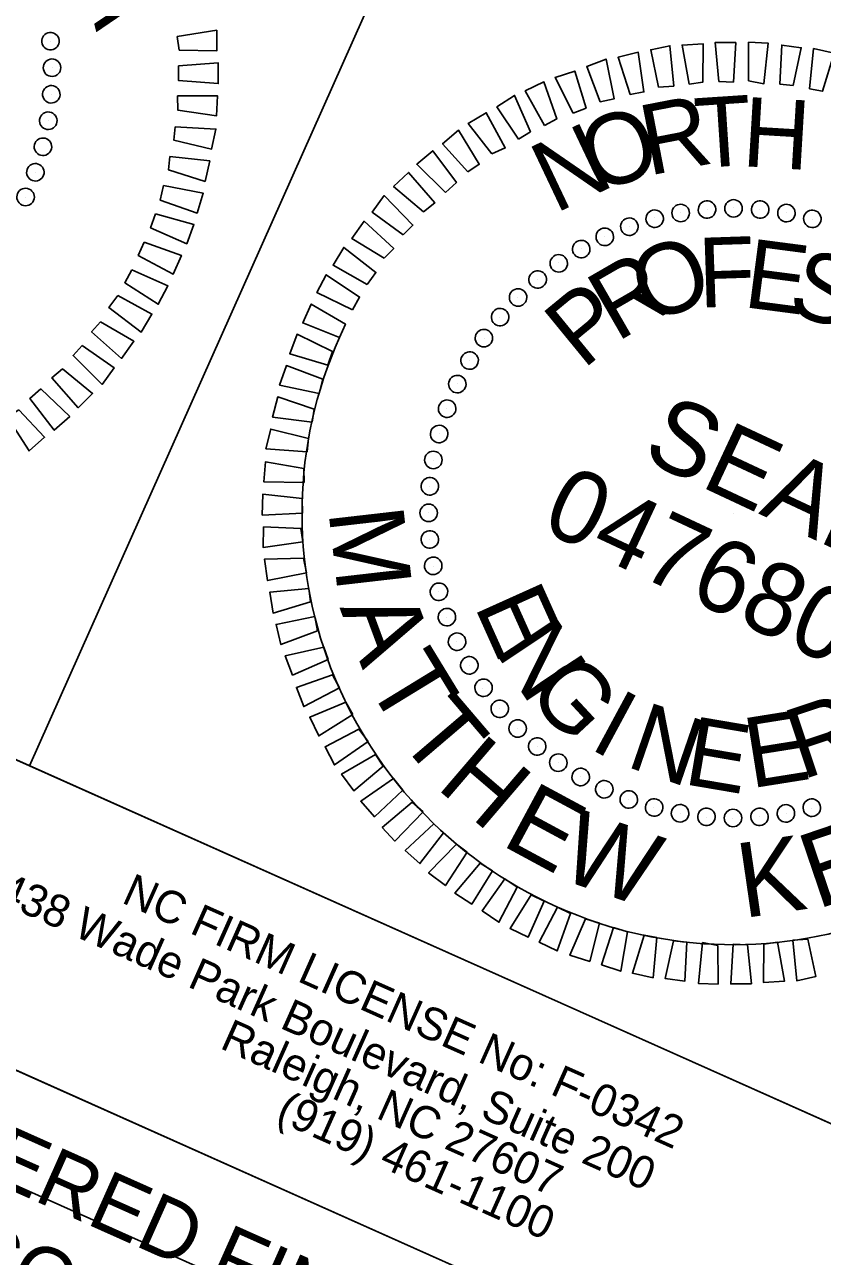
# Model space of a CAD drawing. Extents: x 2297991 to 2299183, y 599186 to 600200.
# Drawn here: x 2299075.6 to 2299120, y 599694 to 599762.5 of the extents above; entities that cross this region are included whole.
import ezdxf

# ---------------------------------------------------------------- set-up
doc = ezdxf.new("R2010")
doc.units = 0
for name, color, linetype in [('Default', 7, 'Continuous'), ('Exist DTM Drainline Cogo Point CELL', 7, 'Continuous'), ('Exist Roads Curbs Cogo Elevation', 7, 'Continuous'), ('Exist Roads Curbs Cogo Number', 7, 'Continuous'), ('Exist Roads EOP Cogo Comment', 7, 'Continuous'), ('Exist Roads EOP Cogo Elevation', 7, 'Continuous'), ('Exist Roads EOP Other Cogo Number', 7, 'Continuous'), ('Exist Roads EOP Other Cogo Point CELL', 7, 'Continuous')]:
    doc.layers.add(name, color=color, linetype=linetype)

# ---------------------------------------------------------------- blocks, each defined once
blk = doc.blocks.new('POINT_DISPLAY')
at = {"layer": 'Default'}
blk.add_line((0, 0), (0, 0), dxfattribs=at)

msp = doc.modelspace()

# ---------------------------------------------------------------- linework, layer by layer
at = {"layer": 'Exist DTM Drainline Cogo Point CELL'}
for points in [[(2299048.604, 599807.413), (2299103.421, 599782.943), (2299075.906, 599721.305), (2299021.089, 599745.774)], [(2299103.421, 599782.943), (2299158.21, 599758.486), (2299130.696, 599696.848), (2299075.906, 599721.305)]]:
    msp.add_lwpolyline(points, close=True, dxfattribs=at)
at = {"layer": 'Exist Roads Curbs Cogo Elevation'}
msp.add_lwpolyline([(2299021.089, 599745.774), (2299130.668, 599696.86), (2299124.249, 599682.479), (2299014.67, 599731.393)], close=True, dxfattribs=at)
at = {"layer": 'Exist Roads Curbs Cogo Number'}
msp.add_line((2299014.67, 599731.393), (2299124.269, 599682.47), dxfattribs=at)
at = {"layer": 'Exist Roads EOP Cogo Comment'}
msp.add_lwpolyline([(2298353.139, 600126.103), (2298108.588, 599578.22), (2298903.031, 599223.593), (2299108.187, 599683.241), (2298998.588, 599732.165), (2299037.976, 599820.403)], close=True, dxfattribs=at)
msp.add_arc((2299115.02, 599735.33), 23.962, 155.94476, 335.94476, dxfattribs=at)
at = {"layer": 'Exist Roads EOP Other Cogo Number'}
for p, q in [((2299112.083, 599752.016), (2299112.083, 599752.016)), ((2299113.57, 599752.202), (2299113.57, 599752.202)), ((2299115.047, 599752.282), (2299115.047, 599752.282)), ((2299116.5, 599752.225), (2299116.5, 599752.225)), ((2299117.96, 599752.017), (2299117.96, 599752.017)), ((2299110.66, 599751.727), (2299110.66, 599751.727)), ((2299119.426, 599751.658), (2299119.426, 599751.658)), ((2299107.879, 599750.714), (2299107.879, 599750.714)), ((2299109.23, 599751.257), (2299109.23, 599751.257)), ((2299106.566, 599750.007), (2299106.566, 599750.007)), ((2299105.3, 599749.241), (2299105.3, 599749.241)), ((2299104.147, 599748.314), (2299104.147, 599748.314)), ((2299103.042, 599747.329), (2299103.042, 599747.329)), ((2299102.033, 599746.227), (2299102.033, 599746.227)), ((2299101.178, 599745.057), (2299101.178, 599745.057)), ((2299100.37, 599743.828), (2299100.37, 599743.828)), ((2299099.673, 599742.513), (2299099.673, 599742.513)), ((2299099.098, 599741.143), (2299099.098, 599741.143)), ((2299098.692, 599739.736), (2299098.692, 599739.736)), ((2299098.333, 599738.27), (2299098.333, 599738.27)), ((2299098.125, 599736.81), (2299098.125, 599736.81)), ((2299098.068, 599735.357), (2299098.068, 599735.357)), ((2299115.02, 599735.33), (2299115.02, 599735.33)), ((2299098.147, 599733.88), (2299098.147, 599733.88)), ((2299098.334, 599732.393), (2299098.334, 599732.393)), ((2299098.623, 599730.97), (2299098.623, 599730.97)), ((2299099.093, 599729.54), (2299099.093, 599729.54)), ((2299099.636, 599728.189), (2299099.636, 599728.189)), ((2299100.343, 599726.876), (2299100.343, 599726.876)), ((2299101.109, 599725.61), (2299101.109, 599725.61)), ((2299102.035, 599724.457), (2299102.035, 599724.457)), ((2299103.02, 599723.352), (2299103.02, 599723.352)), ((2299104.122, 599722.343), (2299104.122, 599722.343)), ((2299105.293, 599721.488), (2299105.293, 599721.488)), ((2299106.522, 599720.68), (2299106.522, 599720.68)), ((2299107.837, 599719.983), (2299107.837, 599719.983)), ((2299109.206, 599719.408), (2299109.206, 599719.408)), ((2299110.614, 599719.001), (2299110.614, 599719.001)), ((2299112.08, 599718.643), (2299112.08, 599718.643)), ((2299113.54, 599718.435), (2299113.54, 599718.435)), ((2299116.47, 599718.457), (2299116.47, 599718.457)), ((2299117.957, 599718.643), (2299117.957, 599718.643)), ((2299119.38, 599718.932), (2299119.38, 599718.932)), ((2299114.993, 599718.377), (2299114.993, 599718.377))]:
    msp.add_line(p, q, dxfattribs=at)
for points in [[(2299109.287, 599758.586), (2299108.622, 599760.657), (2299109.743, 599760.933), (2299110.051, 599758.726)], [(2299110.871, 599758.988), (2299110.432, 599761.069), (2299111.495, 599761.297), (2299111.714, 599759.055)], [(2299112.571, 599759.153), (2299112.173, 599761.327), (2299113.349, 599761.393), (2299113.321, 599759.262)], [(2299114.226, 599759.302), (2299114.01, 599761.468), (2299115.158, 599761.473), (2299115.028, 599759.276)], [(2299115.871, 599759.343), (2299115.868, 599761.489), (2299116.957, 599761.446), (2299116.724, 599759.184)], [(2299117.601, 599759.162), (2299117.718, 599761.328), (2299118.797, 599761.179), (2299118.345, 599759.089)], [(2299119.259, 599758.903), (2299119.479, 599761.133), (2299120.623, 599760.881), (2299119.975, 599758.768)], [(2299107.628, 599758.181), (2299106.877, 599760.143), (2299107.947, 599760.552), (2299108.406, 599758.351)], [(2299106.129, 599757.557), (2299105.121, 599759.522), (2299106.208, 599759.887), (2299106.842, 599757.83)], [(2299104.528, 599756.867), (2299103.462, 599758.784), (2299104.497, 599759.283), (2299105.207, 599757.229)], [(2299103.08, 599756.109), (2299101.884, 599757.899), (2299102.868, 599758.532), (2299103.742, 599756.515)], [(2299101.606, 599755.289), (2299100.292, 599756.984), (2299101.294, 599757.571), (2299102.346, 599755.623)], [(2299100.274, 599754.294), (2299098.862, 599755.848), (2299099.75, 599756.597), (2299100.906, 599754.714)], [(2299099.025, 599753.151), (2299097.431, 599754.713), (2299098.319, 599755.462), (2299099.636, 599753.692)], [(2299097.803, 599752.07), (2299096.14, 599753.478), (2299096.967, 599754.254), (2299098.431, 599752.566)], [(2299096.681, 599750.797), (2299094.949, 599752.051), (2299095.619, 599752.972), (2299097.216, 599751.334)], [(2299095.62, 599749.497), (2299093.819, 599750.596), (2299094.503, 599751.548), (2299096.155, 599750.034)], [(2299094.672, 599748.035), (2299092.782, 599749.1), (2299093.373, 599750.093), (2299095.156, 599748.706)], [(2299093.857, 599746.625), (2299091.881, 599747.58), (2299092.397, 599748.57), (2299094.249, 599747.337)], [(2299093.139, 599745.097), (2299091.094, 599745.899), (2299091.562, 599746.947), (2299093.469, 599745.837)], [(2299092.481, 599743.543), (2299090.368, 599744.19), (2299090.774, 599745.266), (2299092.75, 599744.31)], [(2299092.006, 599741.981), (2299089.81, 599742.444), (2299090.186, 599743.533), (2299092.213, 599742.775)], [(2299091.623, 599740.378), (2299089.42, 599740.659), (2299089.703, 599741.789), (2299091.727, 599741.107)], [(2299091.333, 599738.733), (2299089.044, 599738.905), (2299089.313, 599740.004), (2299091.406, 599739.477)], [(2299091.165, 599737.034), (2299088.928, 599737.072), (2299089.015, 599738.178), (2299091.146, 599737.819)], [(2299091.074, 599735.338), (2299088.842, 599735.225), (2299088.882, 599736.39), (2299091.068, 599736.153)], [(2299091.098, 599733.737), (2299088.891, 599733.429), (2299088.917, 599734.563), (2299090.99, 599734.488)], [(2299091.294, 599732.024), (2299089.138, 599731.582), (2299088.965, 599732.768), (2299091.138, 599732.833)], [(2299091.532, 599730.402), (2299089.444, 599729.782), (2299089.257, 599730.937), (2299091.423, 599731.153)], [(2299091.92, 599728.788), (2299089.883, 599728.034), (2299089.607, 599729.155), (2299091.763, 599729.597)], [(2299092.503, 599727.197), (2299090.531, 599726.34), (2299090.122, 599727.41), (2299092.261, 599727.896)], [(2299093.131, 599725.623), (2299091.152, 599724.584), (2299090.743, 599725.654), (2299092.752, 599726.347)], [(2299093.876, 599724.145), (2299091.979, 599722.959), (2299091.48, 599723.994), (2299093.483, 599724.838)], [(2299094.727, 599722.656), (2299092.85, 599721.35), (2299092.338, 599722.355), (2299094.214, 599723.329)], [(2299095.557, 599721.287), (2299093.941, 599719.902), (2299093.25, 599720.839), (2299095.137, 599721.919)], [(2299096.658, 599719.946), (2299095.076, 599718.471), (2299094.313, 599719.329), (2299096.132, 599720.587)], [(2299097.784, 599718.741), (2299096.208, 599717.116), (2299095.51, 599717.871), (2299097.171, 599719.273)], [(2299098.923, 599717.567), (2299097.608, 599715.863), (2299096.79, 599716.598), (2299098.372, 599718.072)], [(2299100.223, 599716.506), (2299099.021, 599714.641), (2299098.083, 599715.355), (2299099.645, 599716.949)], [(2299101.644, 599715.466), (2299100.486, 599713.617), (2299099.538, 599714.225), (2299100.945, 599715.888)], [(2299103.013, 599714.559), (2299101.996, 599712.611), (2299101.061, 599713.25), (2299102.328, 599715.012)], [(2299104.513, 599713.779), (2299103.619, 599711.775), (2299102.615, 599712.26), (2299103.787, 599714.14)], [(2299105.978, 599713.087), (2299105.238, 599711.015), (2299104.235, 599711.5), (2299105.252, 599713.448)], [(2299107.588, 599712.554), (2299107.047, 599710.43), (2299105.944, 599710.774), (2299106.807, 599712.791)], [(2299109.15, 599712.078), (2299108.763, 599709.886), (2299107.704, 599710.247), (2299108.369, 599712.316)], [(2299110.781, 599711.757), (2299110.561, 599709.526), (2299109.417, 599709.778), (2299110.065, 599711.892)], [(2299119.169, 599711.671), (2299119.608, 599709.591), (2299118.545, 599709.363), (2299118.326, 599711.604)], [(2299112.439, 599711.497), (2299112.322, 599709.332), (2299111.243, 599709.481), (2299111.695, 599711.57)], [(2299114.169, 599711.316), (2299114.172, 599709.171), (2299113.083, 599709.214), (2299113.316, 599711.475)], [(2299115.814, 599711.358), (2299116.03, 599709.192), (2299114.882, 599709.187), (2299115.012, 599711.383)], [(2299117.469, 599711.506), (2299117.867, 599709.333), (2299116.691, 599709.266), (2299116.719, 599711.398)]]:
    msp.add_lwpolyline(points, close=True, dxfattribs=at)
for centre, major_axis in [((2299113.561, 599752.196), (-0.042, 0.484)), ((2299115.036, 599752.259), (0, 0.486)), ((2299116.512, 599752.193), (0.043, 0.484)), ((2299110.654, 599751.686), (-0.125, 0.47)), ((2299112.096, 599752.004), (-0.084, 0.479)), ((2299117.976, 599751.999), (0.085, 0.479)), ((2299119.417, 599751.678), (0.126, 0.469)), ((2299109.245, 599751.243), (-0.166, 0.457)), ((2299107.88, 599750.68), (-0.205, 0.441)), ((2299106.57, 599749.999), (-0.243, 0.421)), ((2299105.323, 599749.207), (-0.278, 0.398)), ((2299104.151, 599748.309), (-0.312, 0.373)), ((2299103.061, 599747.312), (-0.343, 0.344)), ((2299102.062, 599746.224), (-0.372, 0.313)), ((2299101.162, 599745.053), (-0.398, 0.279)), ((2299100.367, 599743.808), (-0.421, 0.243)), ((2299099.684, 599742.499), (-0.44, 0.206)), ((2299099.117, 599741.135), (-0.457, 0.167)), ((2299098.672, 599739.727), (-0.469, 0.126)), ((2299098.351, 599738.286), (-0.479, 0.085)), ((2299098.157, 599736.822), (-0.484, 0.043)), ((2299098.091, 599735.346), (-0.486, 0)), ((2299098.154, 599733.871), (-0.484, -0.042)), ((2299098.345, 599732.406), (-0.479, -0.084)), ((2299098.664, 599730.964), (-0.47, -0.125)), ((2299099.106, 599729.555), (-0.457, -0.166)), ((2299099.67, 599728.19), (-0.441, -0.205)), ((2299100.351, 599726.879), (-0.421, -0.243)), ((2299101.143, 599725.633), (-0.398, -0.278)), ((2299102.041, 599724.461), (-0.373, -0.312)), ((2299103.038, 599723.371), (-0.344, -0.343)), ((2299104.126, 599722.372), (-0.313, -0.372)), ((2299105.297, 599721.472), (-0.279, -0.398)), ((2299106.541, 599720.677), (-0.243, -0.421)), ((2299107.851, 599719.994), (-0.206, -0.44)), ((2299109.215, 599719.427), (-0.167, -0.457)), ((2299110.623, 599718.982), (-0.126, -0.469)), ((2299112.064, 599718.661), (-0.085, -0.479)), ((2299117.944, 599718.655), (0.084, -0.479)), ((2299119.386, 599718.973), (0.125, -0.47)), ((2299113.528, 599718.467), (-0.043, -0.484)), ((2299115.004, 599718.401), (0, -0.486)), ((2299116.479, 599718.464), (0.042, -0.484))]:
    msp.add_ellipse(centre, major_axis=major_axis, ratio=0.999708, dxfattribs=at)
at = {"layer": 'Exist Roads EOP Other Cogo Point CELL'}
for points in [[(2299084.123, 599761.801), (2299086.314, 599762.154), (2299086.318, 599761.006), (2299084.231, 599761.05)], [(2299084.179, 599760.187), (2299086.393, 599760.344), (2299086.398, 599759.196), (2299084.184, 599759.371)], [(2299084.132, 599758.507), (2299086.353, 599758.514), (2299086.295, 599757.394), (2299084.151, 599757.722)], [(2299083.994, 599756.794), (2299086.268, 599756.667), (2299086.028, 599755.553), (2299083.921, 599756.051)], [(2299083.704, 599755.149), (2299085.921, 599754.899), (2299085.669, 599753.754), (2299083.631, 599754.405)], [(2299083.352, 599753.532), (2299085.562, 599753.1), (2299085.218, 599751.997), (2299083.176, 599752.724)], [(2299082.907, 599751.956), (2299085.048, 599751.369), (2299084.643, 599750.294), (2299082.639, 599751.189)], [(2299082.281, 599750.387), (2299084.353, 599749.646), (2299083.886, 599748.599), (2299081.951, 599749.648)], [(2299081.593, 599748.845), (2299083.597, 599747.951), (2299083.067, 599746.931), (2299081.201, 599748.134)], [(2299080.809, 599747.421), (2299082.713, 599746.386), (2299082.122, 599745.394), (2299080.325, 599746.751)], [(2299079.861, 599745.96), (2299081.707, 599744.877), (2299081.022, 599743.925), (2299079.356, 599745.408)], [(2299078.831, 599744.645), (2299080.607, 599743.409), (2299079.938, 599742.487), (2299078.325, 599744.094)], [(2299077.739, 599743.357), (2299079.416, 599741.982), (2299078.62, 599741.19), (2299077.142, 599742.848)], [(2299076.533, 599742.232), (2299078.143, 599740.701), (2299077.284, 599739.938), (2299075.923, 599741.692)], [(2299075.315, 599741.076), (2299076.741, 599739.551), (2299075.884, 599738.788), (2299074.684, 599740.655)]]:
    msp.add_lwpolyline(points, close=True, dxfattribs=at)
for centre, major_axis in [((2299077.07, 599761.547), (0.483, 0.05)), ((2299077.159, 599760.073), (0.486, 0.008)), ((2299077.119, 599758.596), (0.485, -0.034)), ((2299076.95, 599757.129), (0.48, -0.077)), ((2299076.654, 599755.682), (0.472, -0.118)), ((2299076.234, 599754.266), (0.459, -0.159)), ((2299075.691, 599752.892), (0.444, -0.198))]:
    msp.add_ellipse(centre, major_axis=major_axis, ratio=0.999708, dxfattribs=at)

# ---------------------------------------------------------------- block references
at = {"layer": 'Exist Roads EOP Other Cogo Point CELL', "xscale": 41.41195952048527, "yscale": 41.41195952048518, "rotation": -24.05480821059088}
for p in [(2299077.093, 599761.538), (2299077.173, 599760.06), (2299077.146, 599758.593), (2299076.97, 599757.121), (2299076.248, 599754.263), (2299075.705, 599752.88)]:
    msp.add_blockref('POINT_DISPLAY', p, dxfattribs=at)

# ---------------------------------------------------------------- texts
at = {"layer": 'Exist DTM Drainline Cogo Point CELL'}
for s, p in [('HYDRAULICS', (2299118.319, 599771.496)), ('ENGINEER', (2299118.456, 599766.211))]:
    msp.add_text(s, height=3.0001, rotation=335.94476, dxfattribs=at).set_placement(p)
at = {"layer": 'Exist Roads Curbs Cogo Number'}
for s, p in [('DOCUMENT NOT CONSIDERED FINAL', (2299023.684, 599720.572)), ('UNLESS ALL SIGNATURES COMPLETED', (2299018.754, 599716.99))]:
    msp.add_text(s, height=3.30002, rotation=335.94476, dxfattribs=at).set_placement(p)
at = {"layer": 'Exist Roads EOP Cogo Elevation'}
for s, p in [('5438 Wade Park Boulevard, Suite 200', (2299072.776, 599714.346)), ('NC FIRM LICENSE No: F-0342', (2299080.965, 599713.722)), ('Raleigh, NC 27607', (2299086.427, 599705.635)), ('(919) 461-1100', (2299089.529, 599701.632))]:
    msp.add_text(s, height=1.80001, rotation=335.94476, dxfattribs=at).set_placement(p)
at = {"layer": 'Exist Roads EOP Other Cogo Number'}
for s, height, rotation, p in [('R', 3.911, 10.96527, (2299110.301, 599754.068)), ('T', 3.884, 3.76453, (2299113.002, 599754.489)), ('H', 3.854, 356.56424, (2299115.459, 599754.612)), ('O', 3.929, 18.1665, (2299107.321, 599753.107)), ('N', 3.933, 25.36826, (2299105.106, 599751.952)), ('F', 3.876, 1.9118, (2299113.13, 599746.744)), ('O', 3.932, 20.626, (2299110.284, 599745.834)), ('E', 3.839, 352.55583, (2299115.515, 599746.788)), ('R', 3.927, 29.98441, (2299108.531, 599744.805)), ('S', 3.812, 343.20037, (2299117.93, 599746.486)), ('P', 3.897, 39.34365, (2299106.665, 599743.273)), ('SEAL', 4.0489, 334.94476, (2299109.84, 599738.381)), ('047680', 4.0501, 334.94476, (2299104.216, 599734.453)), ('M', 4.162, 276.53931, (2299092.516, 599735.461)), ('E', 3.927, 294.22165, (2299100.605, 599730.196)), ('A', 4.183, 290.35425, (2299093.135, 599730.084)), ('N', 3.902, 303.57872, (2299101.712, 599727.706)), ('T', 4.159, 301.43128, (2299094.551, 599725.977)), ('G', 3.864, 312.935, (2299103.435, 599725.274)), ('T', 4.122, 310.43126, (2299096.266, 599722.89)), ('I', 3.808, 331.64596, (2299106.949, 599722.3)), ('N', 3.809, 341.00115, (2299108.973, 599721.286)), ('R', 3.929, 18.42617, (2299118.827, 599720.51)), ('E', 3.831, 350.35652, (2299112.189, 599720.294)), ('E', 3.905, 9.06885, (2299115.992, 599720.038)), ('H', 4.084, 319.43124, (2299098.443, 599720.109)), ('E', 4.051, 331.67267, (2299102.047, 599716.941)), ('W', 4.052, 340.98736, (2299105.194, 599715.083)), ('E', 4.18, 18.79736, (2299119.669, 599713.311)), ('K', 4.151, 8.2868, (2299115.575, 599712.832))]:
    msp.add_text(s, height=height, rotation=rotation, dxfattribs=at).set_placement(p)
at = {"layer": 'Exist Roads EOP Other Cogo Point CELL'}
msp.add_text('A', height=3.806, rotation=284.00731, dxfattribs=at).set_placement((2299078.802, 599765.327))

doc.saveas('drawing.dxf')
